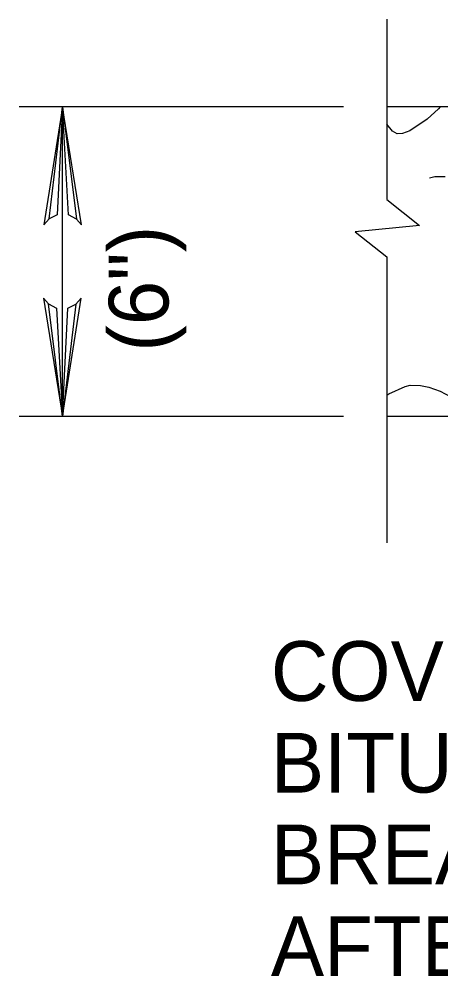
# Model space of a CAD drawing. Extents: x 638455 to 640199, y 298558 to 299152.
# Drawn here: x 638549.1 to 638572.8, y 298648.1 to 298702 of the extents above; entities that cross this region are included whole.
import ezdxf

# ---------------------------------------------------------------- set-up
doc = ezdxf.new("R2010")
doc.units = 0
doc.layers.add('2', color=7, linetype='Continuous')
doc.layers.add('3', color=7, linetype='Continuous')

msp = doc.modelspace()

# ---------------------------------------------------------------- linework, layer by layer
at = {"layer": '2'}
for p, q in [((638569.754, 298701.969), (638569.754, 298691.826)), ((638567.315, 298697.041), (638549.054, 298697.041)), ((638551.494, 298679.617), (638551.494, 298697.041)), ((638610.593, 298697.041), (638569.754, 298697.041)), ((638569.754, 298688.602), (638569.754, 298672.503)), ((638567.315, 298679.617), (638549.054, 298679.617)), ((638691.649, 298679.617), (638569.754, 298679.617))]:
    msp.add_line(p, q, dxfattribs=at)
for points in [[(638552.287, 298690.714), (638551.828, 298690.949), (638551.494, 298697.041), (638552.287, 298690.714), (638552.565, 298690.388), (638551.494, 298697.041), (638551.192, 298690.955), (638550.739, 298690.731), (638551.494, 298697.041), (638550.434, 298690.388), (638550.739, 298690.731)], [(638572.745, 298697.041), (638572.649, 298696.914)], [(638572.649, 298696.914), (638572.022, 298696.336)], [(638570.074, 298695.674), (638569.754, 298696.06)], [(638572.022, 298696.336), (638571.044, 298695.691)], [(638570.32, 298695.525), (638570.074, 298695.674)], [(638570.628, 298695.534), (638570.32, 298695.525)], [(638571.044, 298695.691), (638570.628, 298695.534)], [(638572.156, 298693.045), (638572.452, 298693.118)], [(638572.452, 298693.118), (638573.033, 298693.112)], [(638569.754, 298691.826), (638571.589, 298690.35), (638567.962, 298689.999), (638569.754, 298688.602)], [(638550.698, 298685.948), (638551.157, 298685.71), (638551.494, 298679.617), (638550.698, 298685.948), (638550.419, 298686.271), (638551.494, 298679.617), (638551.793, 298685.707), (638552.246, 298685.928), (638551.494, 298679.617), (638552.551, 298686.271), (638552.246, 298685.928)], [(638569.754, 298680.814), (638569.862, 298680.886)], [(638569.862, 298680.886), (638570.77, 298681.296)], [(638570.77, 298681.296), (638571.067, 298681.368)], [(638571.067, 298681.368), (638571.647, 298681.363)], [(638571.647, 298681.363), (638572.101, 298681.27)], [(638572.101, 298681.27), (638572.754, 298681.028)], [(638572.754, 298681.028), (638573.303, 298680.732)]]:
    msp.add_lwpolyline(points, dxfattribs=at)

# ---------------------------------------------------------------- texts
at = {"layer": '3'}
msp.add_text('(6")', height=3.36, rotation=90, dxfattribs=at).set_placement((638557.457, 298683.254))
for s, p in [('COVER WITH 2-PLY', (638563.22, 298663.606)), ('BITUMINOUS PAPER AND', (638563.22, 298658.446)), ('BREAK THROUGH HOLE', (638563.22, 298653.286)), ('AFTER COMPLETION.', (638563.22, 298648.126))]:
    msp.add_text(s, height=3.36, dxfattribs=at).set_placement(p)

doc.saveas('drawing.dxf')
